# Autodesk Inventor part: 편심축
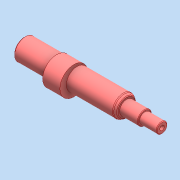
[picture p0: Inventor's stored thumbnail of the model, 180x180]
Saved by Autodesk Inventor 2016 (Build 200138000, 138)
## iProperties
Created: 2024-08
Part Number: 편심축
Material: 일반
Document SubType Name: Modeling
Designer: pc-7
Density: 1 g/cm^3
Appearance: 기본값
Author: jhkim
Sending System: Autodesk Inventor 2025
Preprocessor: ST-DEVELOPER v20
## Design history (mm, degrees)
node "편심축1"
node "솔리드2"
node "솔리드1"
